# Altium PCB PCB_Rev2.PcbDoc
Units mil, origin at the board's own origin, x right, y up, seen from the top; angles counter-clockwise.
Board outline 1750.01 x 1055 mil, 4 copper layers (Top Layer, Layer 1 (GND), Layer 2 (PWR), Bottom Layer), stack 51.556 mil thick; 67 components, 50 nets, 281 pads, 118 vias.
Unrouted connection lines stored in the file: 3.
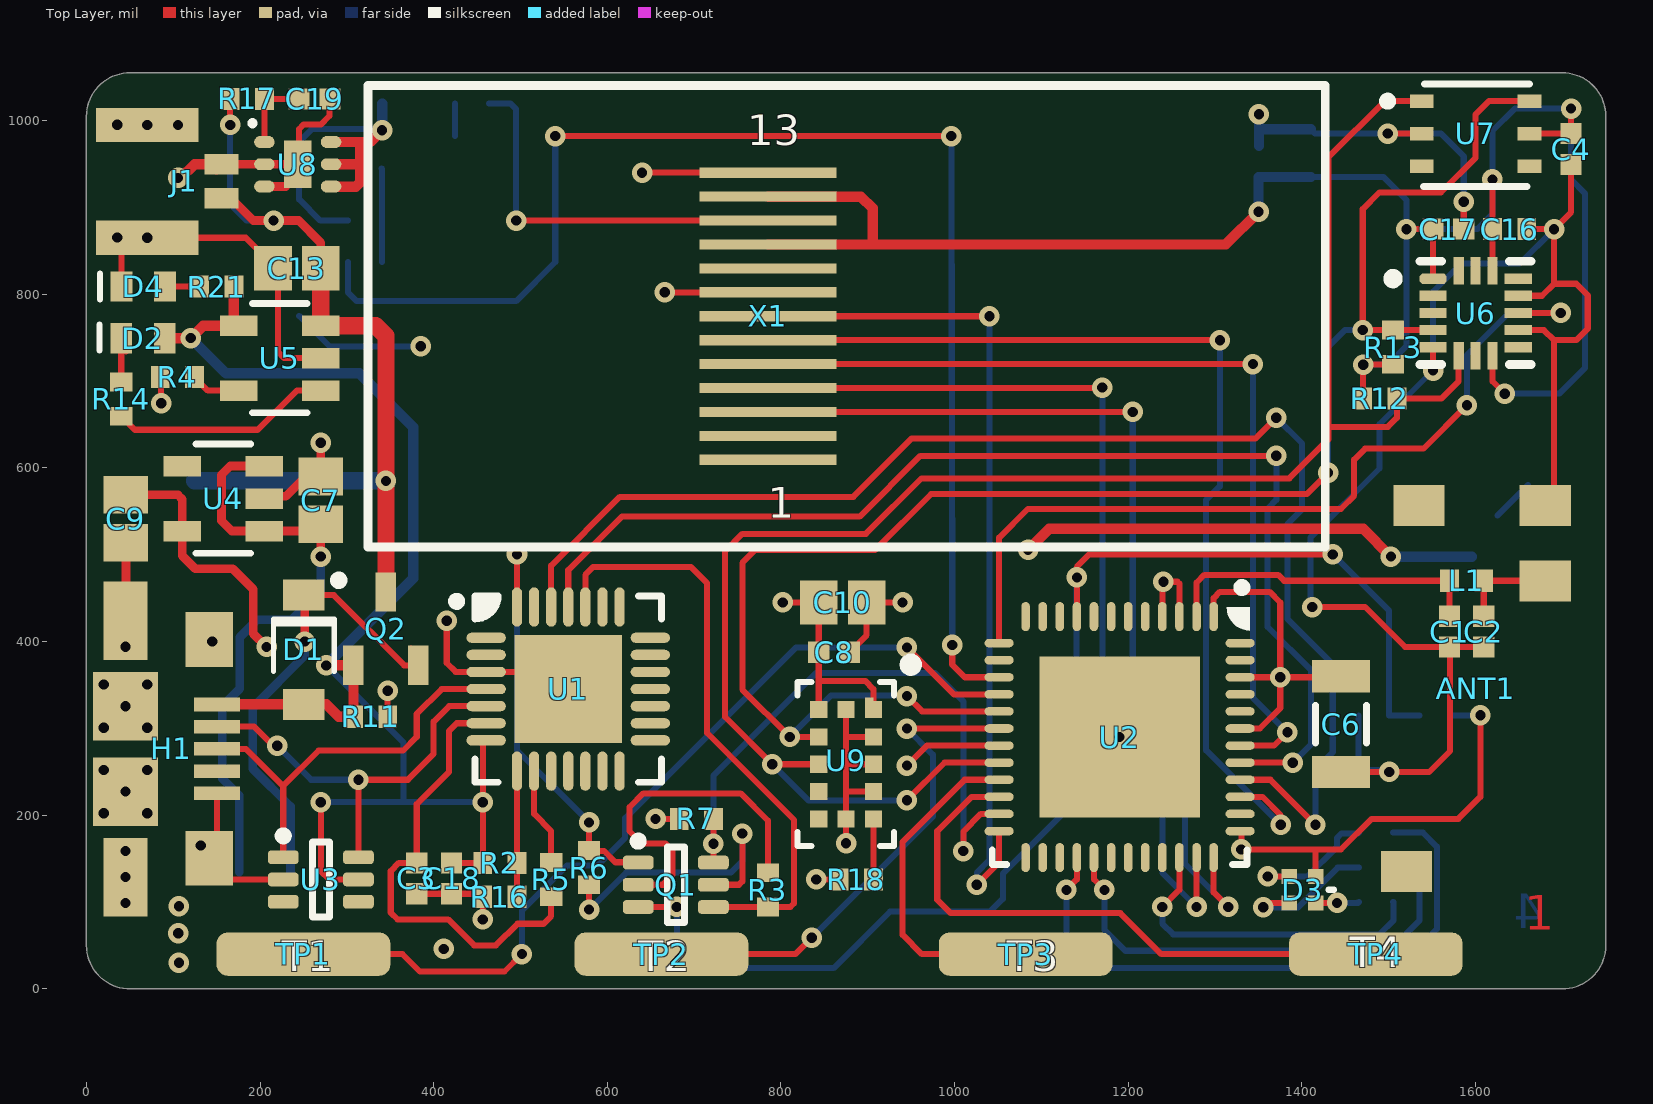
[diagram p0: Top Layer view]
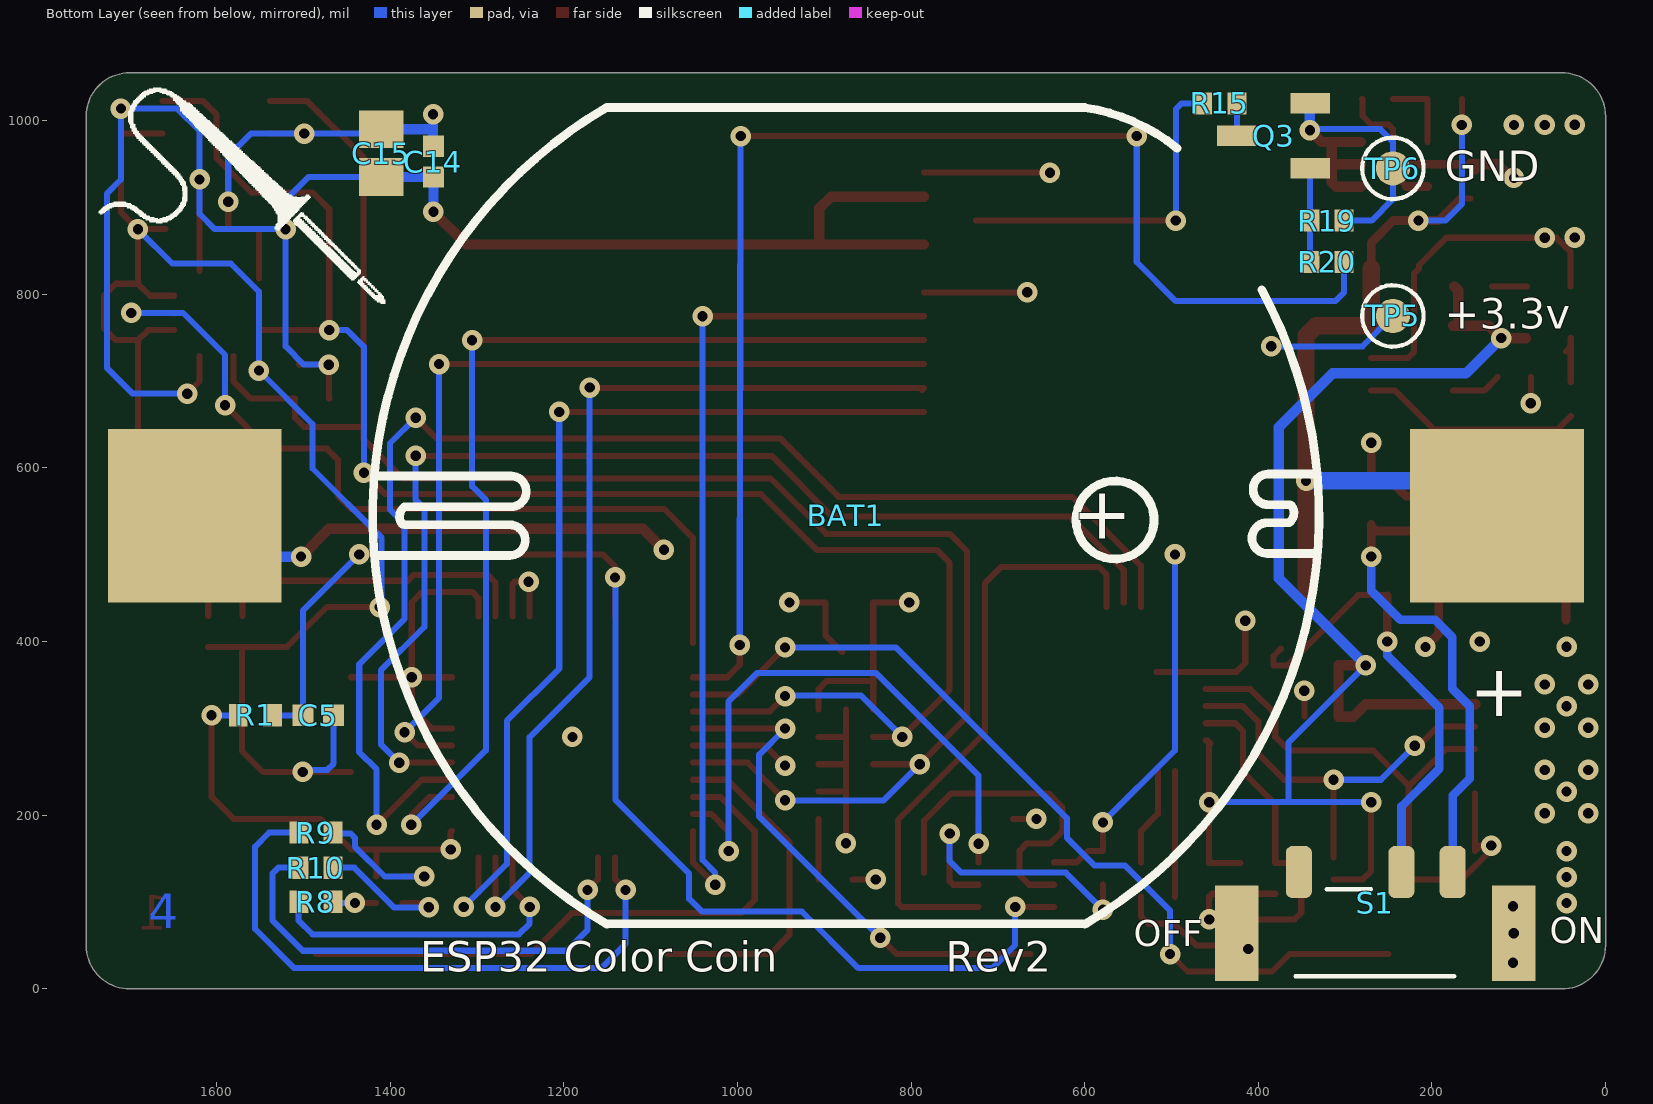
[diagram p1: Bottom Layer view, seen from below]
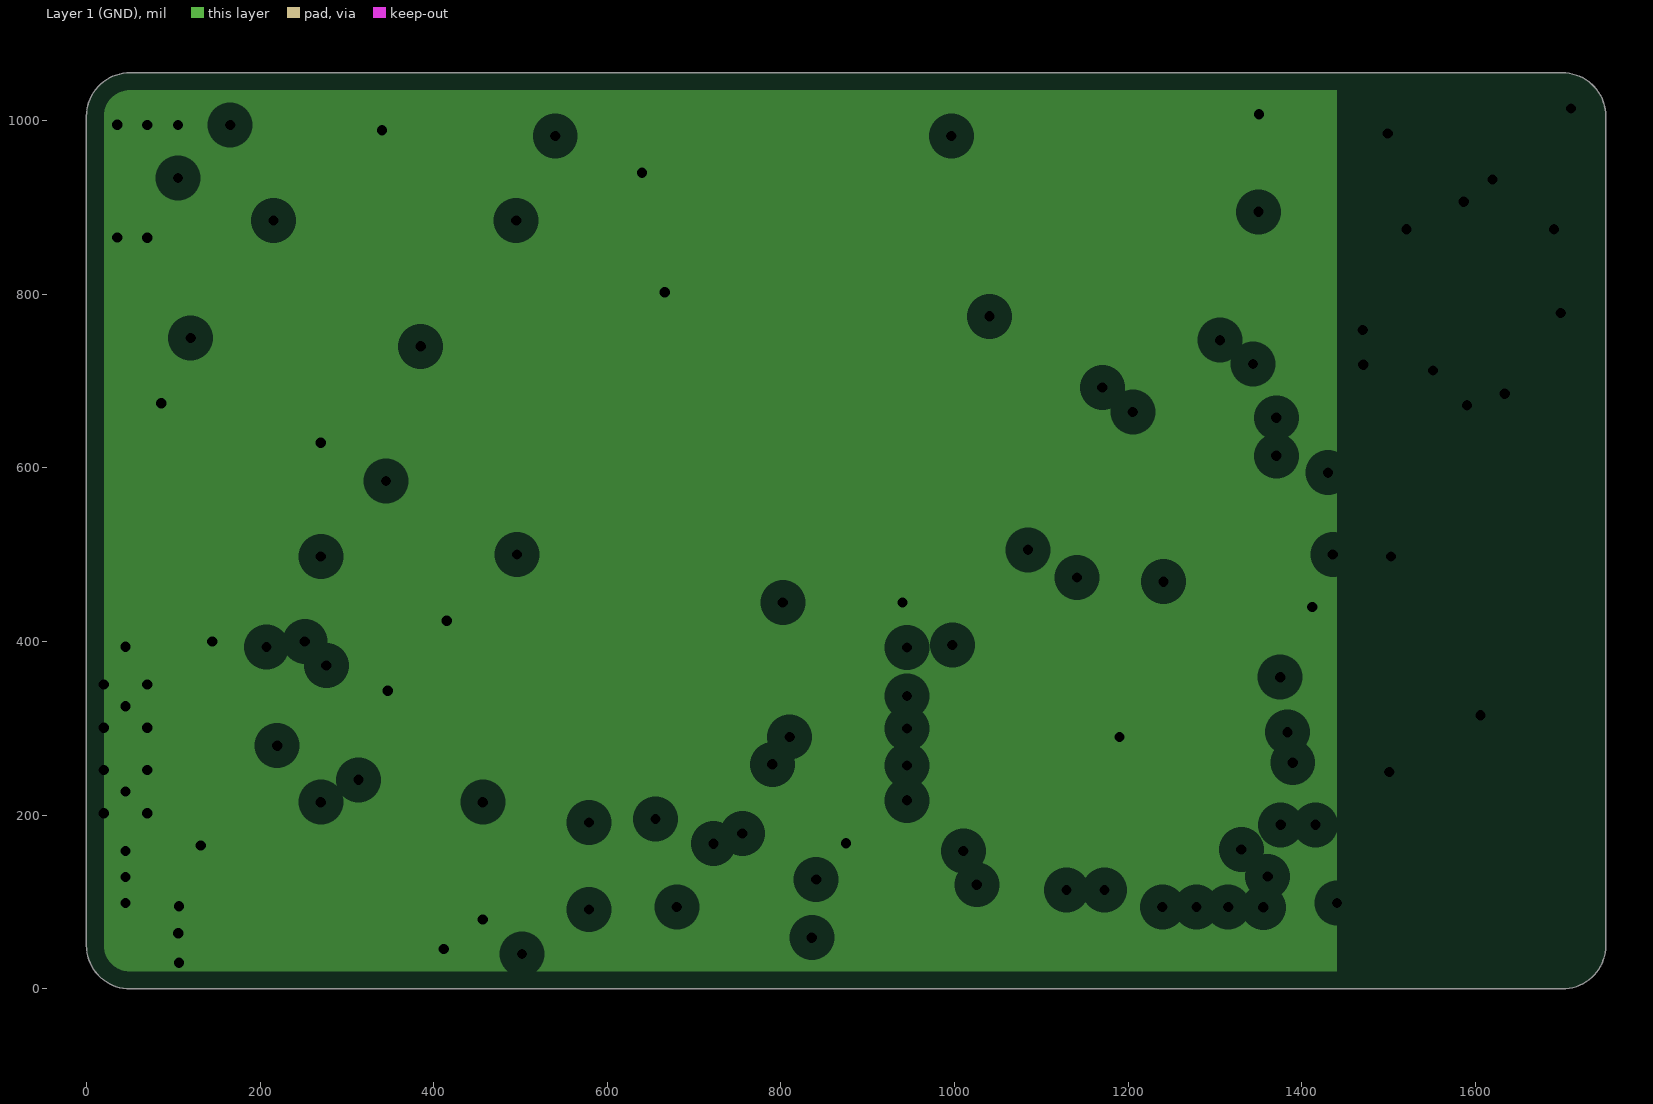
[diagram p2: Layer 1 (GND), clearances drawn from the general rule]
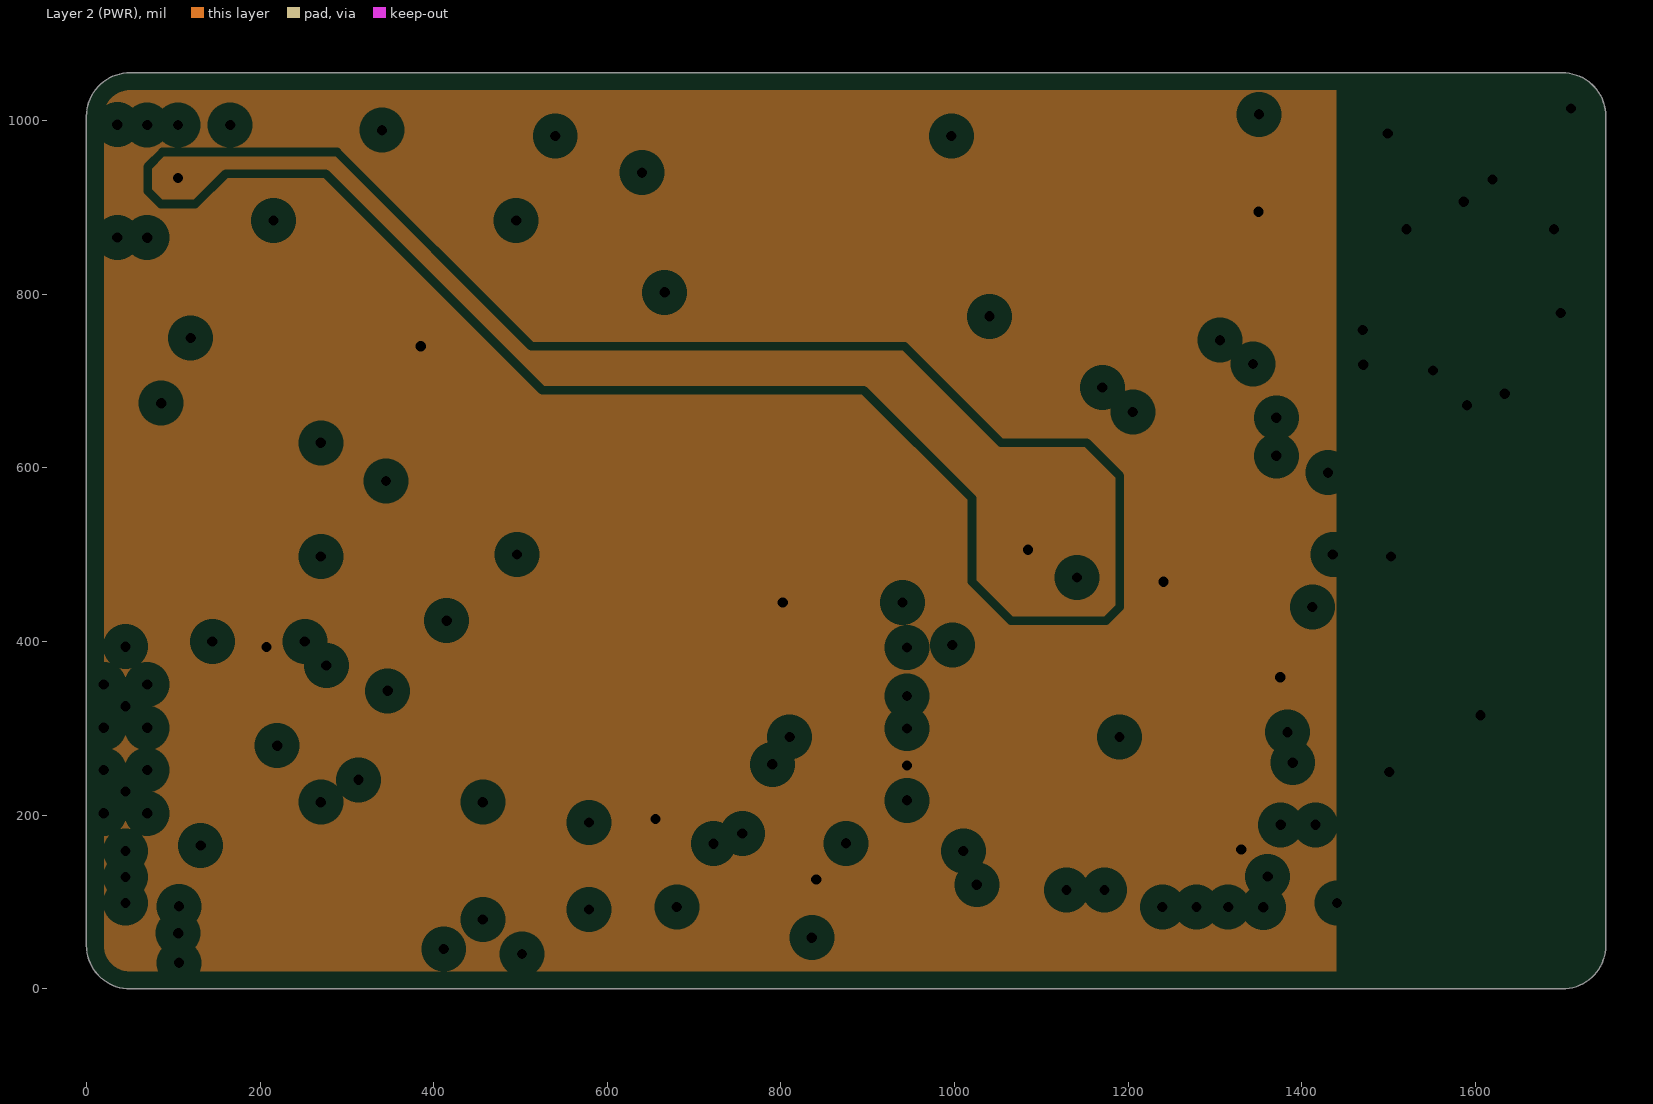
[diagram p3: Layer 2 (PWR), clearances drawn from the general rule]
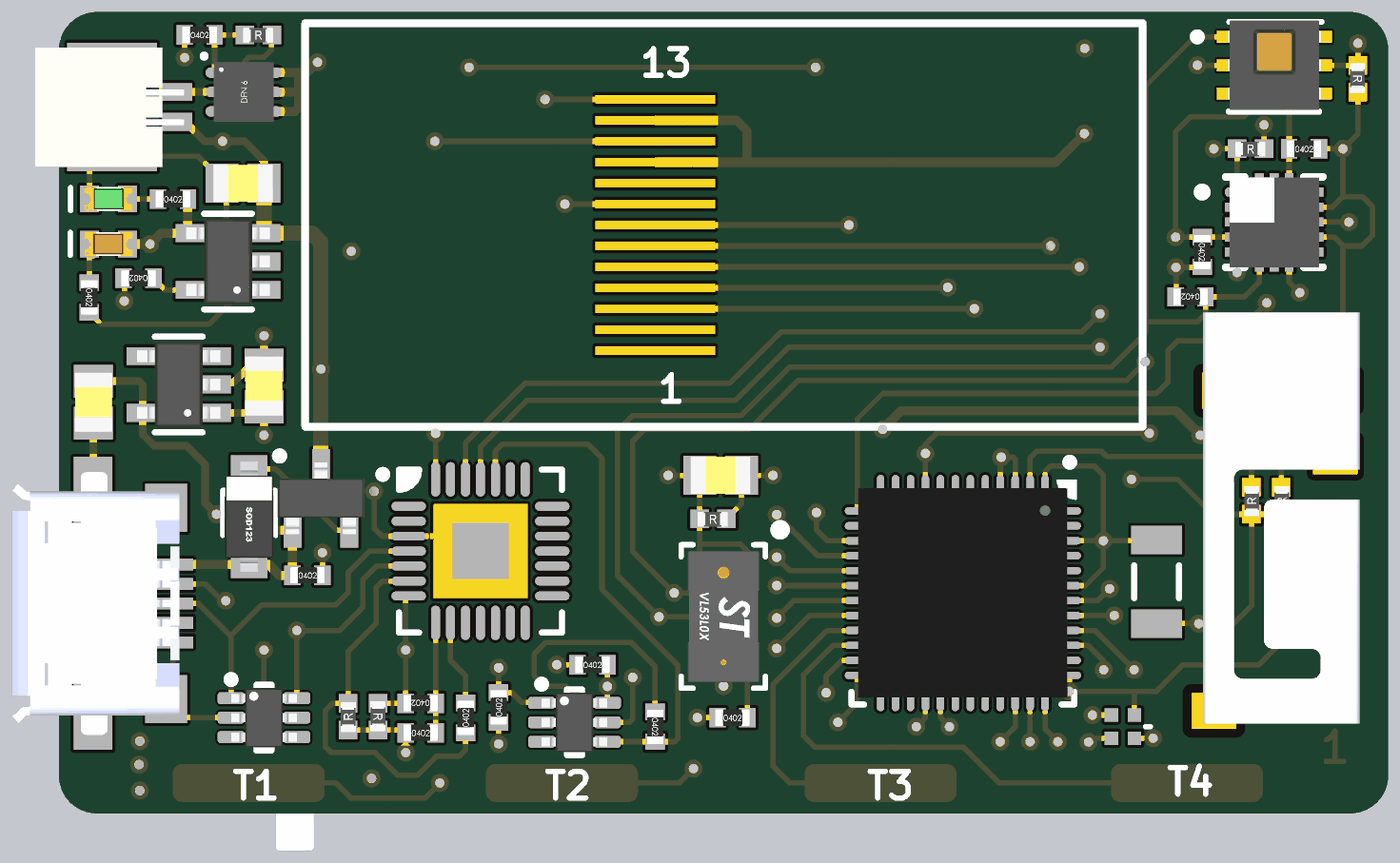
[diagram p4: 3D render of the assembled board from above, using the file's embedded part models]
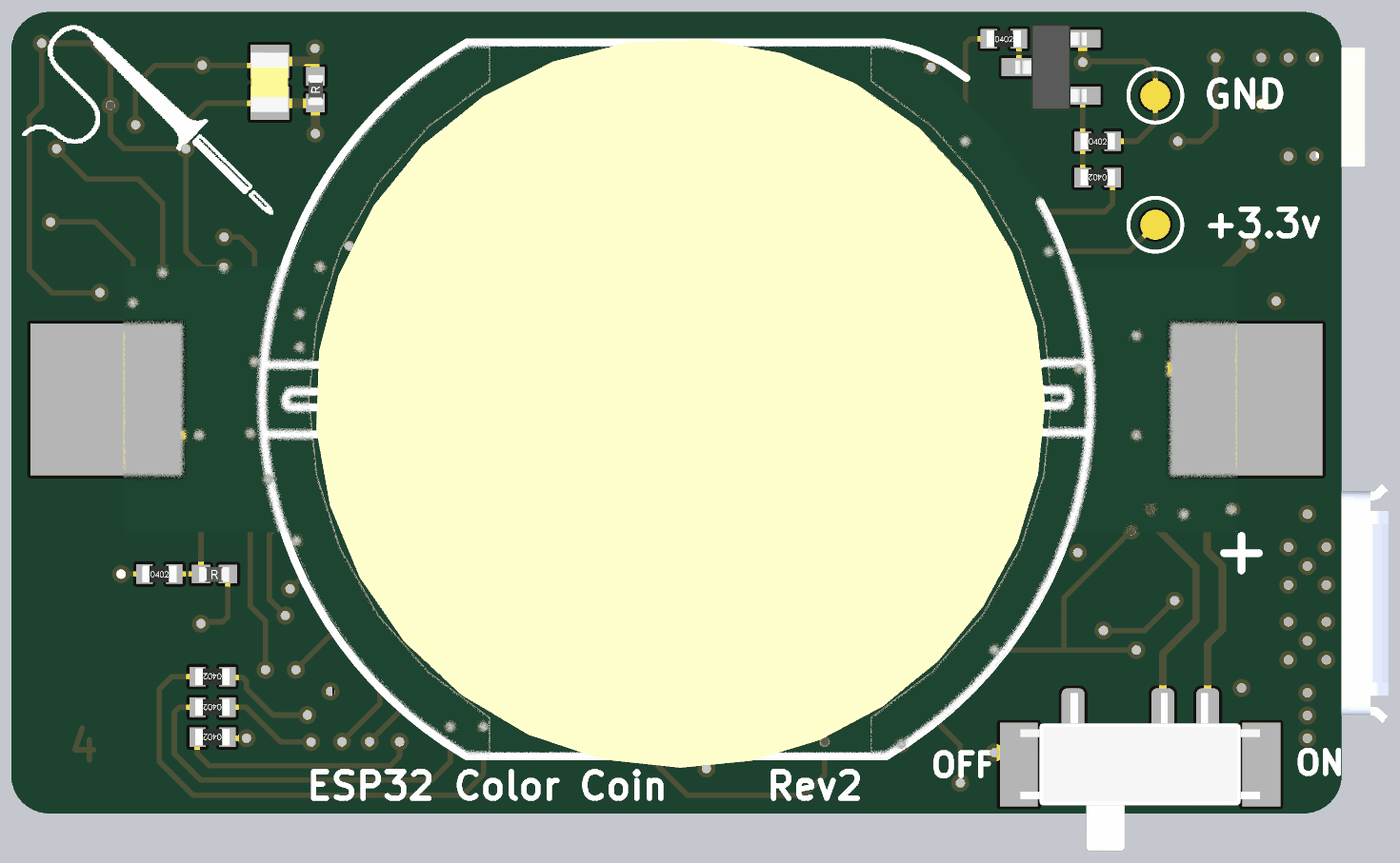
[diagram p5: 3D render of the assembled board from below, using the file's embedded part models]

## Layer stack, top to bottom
Top Solder: solder mask 0.4, Solder Resist, Dk 3.5
Top Layer: signal copper 1.4
Dielectric 2: prepreg 2.8, PP-006, Dk 4.1
Layer 1 (GND): plane copper 1.3778, net GND
Dielectric 1: dielectric 40.4, FR-4, Dk 4.8
Layer 2 (PWR): plane copper 1.3778, net (Multiple Nets)
Dielectric 3: prepreg 2.8, PP-006, Dk 4.1
Bottom Layer: signal copper 1.4
Bottom Solder: solder mask 0.4, Solder Resist, Dk 3.5

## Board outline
50.5,0 cw(c50,50) 0,50 0,1005 cw(c50,1005) 50.5,1055 1699.49,1055 cw(c1699.99,1005.01) 1749.99,1005.01 1750.01,50 cw(c1700.01,50) 1699.51,0

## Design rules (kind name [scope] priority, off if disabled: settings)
Clearance Clearance_U7 [All vs InComponent('U7')] p1: gap=7 ignorepadtopadclearanceinfootprint=FALSE
Clearance Clearance_H1 [All vs InComponent('H1')] p2: gap=9.5 ignorepadtopadclearanceinfootprint=FALSE
Clearance Clearance_U3 [All vs InComponent('U3')] p3: gap=9.5 ignorepadtopadclearanceinfootprint=FALSE
Clearance Clearance_Q1 [All vs InComponent('Q1')] p4: gap=9.5 ignorepadtopadclearanceinfootprint=FALSE
Clearance Clearance_X1 [All vs InComponent('X1')] p5: gap=8.5 ignorepadtopadclearanceinfootprint=FALSE
Clearance Clearance_U2 [All vs InComponent('U2')] p6: gap=9.5 ignorepadtopadclearanceinfootprint=FALSE
Clearance Clearance_U1 [All vs InComponent('U1')] p7: gap=7.8 ignorepadtopadclearanceinfootprint=FALSE
Clearance Clearance_U6 [All vs InComponent('U6')] p8: gap=7.5 ignorepadtopadclearanceinfootprint=FALSE
Clearance [All] p9: gap=10 ignorepadtopadclearanceinfootprint=FALSE except(0: Arc-Hole Track-Hole SMDPad-Hole THPad-Hole Via-Hole Fill-Hole Poly-Hole Region-Hole Text-Hole)
HoleSize [All] p1: absolutevalues=TRUE maxlimit=200 minlimit=1 maxpercent=80.000 minpercent=20.000
MinimumSolderMaskSliver MinimumSolderMaskSliver_X1 [All vs InComponent('X1')] p1: minsoldermaskwidth=0.6
MinimumSolderMaskSliver [All] p2: minsoldermaskwidth=1
PlaneClearance [All] p1: clearance=20
PlaneConnect [All] p1: planeconnectstyle=Direct reliefexpansion=20 reliefentries=4 reliefconductorwidth=10 reliefairgap=10
PolygonConnect [All] p1: connectstyle=Relief reliefconductorwidth=10 reliefentries=4 polygonreliefangle="90 Angle" airgapwidth=10
RoutingVias [All] p1: holewidth=11.81 width=23.62 viastyle="Through Hole" minholewidth=11.81 minwidth=23.62 maxholewidth=11.81 maxwidth=23.62
SilkToSilkClearance [All] p1: silktosilkclearance=5
SilkToSolderMaskClearance [IsPad] p1: minsilkscreentomaskgap=5 clearancetoexposedcopper=TRUE
SolderMaskExpansion [All] p1: expansion=4
Width [All] p1: maxlimit=40 minlimit=7 preferedwidth=7
24 further rules are at their usual default settings.

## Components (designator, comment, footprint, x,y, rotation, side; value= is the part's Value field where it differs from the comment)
ANT1 "RF ANT 2.4GHZ STAMPED MET SLD" PRO-OB-440 1680.37,556.61 r0 top locked
BAT1 "BATTERY-HOLDER (2450)" BU2450SM-JJ-GTR 875,545 r0 bottom locked value="Coin Cell Holder"
C1 "=Value" CAPC1005X56N#1 1570,411.5 r90 top
C2 "=Value" CAPC1005X56N#1 1609.37,411.5 r90 top
C3 "4.7uF" CAPC1005X56N#2 380.51,127.28 r90 top
C4 "0.1uF" CAPC1005X56N#1 1710,967.28 r270 top
C5 "0.1uF" CAPC1005X56N#2 1482.72,315 r180 bottom
C6 "100uF" CAPC3216X160L 1445,304.88 r270 top
C7 "10uF" CAPC2012X140N 270,562.56 r90 top
C8 "0.1uF" CAPC1005X56N#2 861.22,387.76 r0 top
C9 "10uF" CAPC2012X140N 45.51,541.34 r270 top
C10 "10uF" CAPC2012X140N 871.06,445 r0 top
C13 "10uF" CAPC2012X140N 242.44,829.76 r180 top
C14 "0.1uF" CAPC1005X56N#2 1350,952.72 r90 bottom
C15 "10uF" CAPC2012X140N 1410,962.56 r90 bottom
C16 "0.1uF" RESC1005X40L 1639.14,875 r0 top
C17 "0.1uF" CAPC1005X56N#2 1568.67,875 r0 top
C18 "1uF" CAPC1005X56N#2 420.51,127.28 r270 top
C19 "0.1uF" CAPC1005X56N#2 262.72,1025 r0 top
D1 "MBR0520" SOD123 250.51,390.56 r270 top
D2 "LED_0603" LED1608X55N-RED 65.14,749.53 r0 top value=Red
D3 "RGB" FC-B1010RGBT-HG 1400.77,114.15 r0 top value="RGB Led"
D4 "LED_0603" LED1608X55N-GREEN 65.51,808.9 r0 top locked value=Green
H1 "Micro USB" 1981584-1 97.66,276.38 r270 top
J1 "CON2" JST_Micro_2PIN 155.63,930.04 r270 top
L1 "Inductor" RESC1005X40L 1589.69,470 r180 top value=1.8nH
Q1 "BC847S" SOT65P210X110-6N 678.82,118.9 r0 top value=2NPN
Q2 "FDN340P" SOT95P240X110-3N 345,414.84 r90 top value="Mosfet P-H"
Q3 "MMBT3904" SOT95P240X110-3N 382.33,982.4 r0 bottom locked
R1 "10K" RESC1005X40L 1555.12,315 r180 bottom
R2 "22.1K" RESC1005X40L 476.26,145 r180 top
R3 "10K" RESC1005X40L 785,113.98 r270 top
R4 "43K" RESC1005X40L 104.83,704.53 r180 top
R5 "4.7K" RESC1005X40L 535.32,125.79 r90 top
R6 "10K" RESC1005X40L 578.94,139.57 r90 top
R7 "10K" RESC1005X40L 702.44,195.67 r0 top
R8 "1K" RESC1005X40L 1485.32,100.21 r0 bottom
R9 "1K" RESC1005X40L 1485.32,180 r0 bottom
R10 "1K" RESC1005X40L 1485.32,139.58 r0 bottom
R11 "100K" RESC1005X40L 327.28,313.5 r0 top
R12 "2K" RESC1005X40L 1489.69,680 r180 top
R13 "2K" RESC1005X40L 1505,739.06 r270 top
R14 "2K" RESC1005X40L 40.14,679.21 r270 top
R15 "22R" RESC1005X40L 444.33,1019.8 r180 bottom
R16 "47.5K" RESC1005X40L 476.26,106.1 r0 top
R17 "100R" RESC1005X40L 185.32,1025 r0 top
R18 "10K" RESC1005X40L 886.81,125.98 r0 top
R19 "10K" RESC1005X40L 320.83,884.88 r180 bottom
R20 "1K" RESC1005X40L 320.83,837.17 r0 bottom
R21 "2K" RESC1005X40L 150.32,808.9 r0 top
S1 "SWITCH SLIDE" K3-1296S-E1 265.14,99.53 r180 bottom
TP1 "Test Point, 1mm Top Layer" TP100TL#1 302.06,-135 r90 top
TP2 "Test Point, 1mm Top Layer" TP100TL#2 662.28,40 r90 top
TP3 "Test Point, 1mm Top Layer" TP100TL#3 580,-145 r90 top
TP4 "Test Point, 1mm Top Layer" TP100TL#4 945.51,-121.1 r90 top
TP5 "Test Point, 1mm Top Layer" TP100TL#5 245,775 r90 bottom
TP6 "Test Point, 1mm Top Layer" TP100TL#5 245,945 r90 bottom
U1 "CP2102N" 28-QFN 555,345.28 r0 top locked
U2 "ESP32-PICO-D4" QFN48 1190,290 r270 top locked
U3 "PESD5V0L5UY" SOT65P210X110-6N 270,125 r0 top value=ESD
U4 "HT7833" SOT95P280X144-5N 157.76,564.69 r180 top value="LDO 3.3V"
U5 "SL4054ST25P" SOT95P280X144-5N 222.76,726.5 r180 top
U6 "LIS3DHTR" QFN3X3_16_1.2 1599.96,777.99 r0 top
U7 "HDC1080DMBT" HDC1080 1600,985 r0 top value=Humidity/Temperature
U8 "XB6566H0" "DFN-6 2x2mm" 243.39,949.72 r0 top value="Battery Protection"
U9 "VL53L0CXV0DH" VL53L0CXV0DH 875,263.09 r0 top locked
X1 "TFT_0.96 inch" "TFT_GLASS 0.96 INCH" 966.1,774.65 r90 top locked

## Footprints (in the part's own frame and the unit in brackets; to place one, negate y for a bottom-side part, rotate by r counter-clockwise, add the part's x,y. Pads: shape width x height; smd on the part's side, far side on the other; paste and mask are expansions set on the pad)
28-QFN [mm] "QFN, 28-Leads, Body 5.00x5.00mm, Pitch 0.50mm, Thermal Pad 3.15x3.15mm, IPC Medium Density"
  oval 1.15x0.3 smd: 1(-2.4,1.5) 2(-2.4,1) 3(-2.4,0.5) 4(-2.4,0) 5(-2.4,-0.5) 6(-2.4,-1) 7(-2.4,-1.5) 15(2.4,-1.5) 16(2.4,-1) 17(2.4,-0.5) 18(2.4,0) 19(2.4,0.5) 20(2.4,1) 21(2.4,1.5)
  oval 0.3x1.15 smd: 8(-1.5,-2.4) 9(-1,-2.4) 10(-0.5,-2.4) 11(0,-2.4) 12(0.5,-2.4) 13(1,-2.4) 14(1.5,-2.4) 22(1.5,2.4) 23(1,2.4) 24(0.5,2.4) 25(0,2.4) 26(-0.5,2.4) 27(-1,2.4) 28(-1.5,2.4)
  rect 3.15x3.15 smd paste-0.635: 29(0,0)
  silkscreen extent -3.39,-2.73 2.73,2.73, body extent -2.58,-2.57 2.57,2.58, height 1
1981584-1 [mm] "CONN RCPT MICRO USB TYPE AB"
  rect 0.4x1.35 smd: 1(-1.3,1.338) 2(-0.65,1.338) 3(0,1.338) 4(0.65,1.338) 5(1.3,1.338)
  rect 2.3x1.3 smd: 6(-3.75,-1.337) 6(3.75,-1.337)
  rect 1.6x1.4 smd: 6(-3.2,1.113) 6(3.2,1.113)
  rect 2x1.9 smd: 6(-1.25,-1.337) 6(1.25,-1.337)
  body extent -4.4,-4.05 4.4,1.55, height 2.75
BU2450SM-JJ-GTR [mil] "HOLDER,BATT,COIN,24.5MM,SMT"
  rect 200x200 smd: 1(-750,0) 2(750,0)
  silkscreen extent -545,-470 545,470, body extent -842,-570 3485,485, height 291
CAPC1005X56N#1 [mm] "Chip Capacitor, 2-Leads, Body 1.0x0.5mm, IPC Medium Density (0402 ceramic)"
  rect 0.62x0.62 smd paste-0.305: 1(-0.45,0) 2(0.45,0)
  body extent -0.55,-0.3 0.55,0.3, height 0.6
CAPC1005X56N#2 [mm] "Chip Capacitor, 2-Leads, Body 1.0x0.5mm, IPC Medium Density (0402 ceramic)"
  rect 0.62x0.62 smd: 1(-0.45,0) 2(0.45,0)
  body extent -0.55,-0.3 0.55,0.3, height 0.6
CAPC2012X140N [mm] "Chip Capacitor, 2-Leads, Body 2.0x1.3mm, IPC Medium Density (0805 ceramic)"
  rect 1.1x1.3 smd: 1(-0.7,0) 2(0.7,0)
  body extent -1,-0.62 1,0.63, height 1.24
CAPC3216X160L [mm] "Chip Capacitor, 2-Leads, Body 3.2x1.6mm, IPC Least Density(C1206)"
  rect 0.95x1.7 smd: 1(-1.4,0) 2(1.4,0)
  silkscreen extent -0.55,-0.75 0.55,0.75, body extent -1.7,-0.9 1.7,0.9, height 1.9
"DFN-6 2x2mm" [mm] "DFN, 6-Leads, Body 2.00x2.00mm, Pitch 0.65mm, IPC High Density"
  oval 0.6x0.35 smd: 1(-0.975,0.65) 2(-0.975,0) 3(-0.975,-0.65) 4(0.975,-0.65) 5(0.975,0) 6(0.975,0.65)
  rect 0.8x1.4 smd paste-0.15: 7(0,0)
  silkscreen extent -1.37,1.15 -1.27,1.25, body extent -1,-1 2.65,1, height 4.99
FC-B1010RGBT-HG [mm] "LED,RGB,SMD,RoHS"
  rect 0.45x0.45 smd: 1(0.387,0.388) 2(0.387,-0.387) 3(-0.387,-0.387) 4(-0.387,0.388)
  silkscreen extent 0.76,0 0.91,0, body extent -0.53,-0.55 0.53,0.58, height 1.2
HDC1080 [mm] "Temp/Humidity Sensor"
  rect 0.7x0.4 smd paste-0.381 mask+0.076: 1(-1.575,0.95) 2(-1.575,0) 3(-1.575,-0.95) 4(1.575,-0.95) 5(1.575,0) 6(1.575,0.95)
  silkscreen extent -2.7,-1.55 1.57,1.45, body extent -1.55,-1.5 1.55,1.5, height 0.85
JST_Micro_2PIN [mm]
  rect 0.6x1 smd: 1(0.5,0) 2(-0.5,0)
  rect 1x3 smd: ""(-1.65,-2.175) ""(1.65,-2.175)
  body extent -1.99,-4.74 2,0.24, height 2.9
K3-1296S-E1 [mil] "Toggle Switches SMD RoHS"
  rrect50% 30x60 smd: 1(89.06,35) 2(30,35) 3(-88.11,35)
  rect 50x110 smd: 4(-159.45,-35.43) 4(159.45,-35.43)
  silkscreen extent -92,-85 91,15, body extent -157,-149 158,59, height 60
LED1608X55N-GREEN [mil] "Chip LED GREEN 2-Leads, Body 1.6x0.8mm, IPC Medium Density (0603 med)"
  rect 25x35 smd: 1(-25,0) 2(25,0)
  body extent -31,-16 32,16, height 24
LED1608X55N-RED [mil] "Chip LED RED, 2-Leads, Body 1.6x0.8mm, IPC Medium Density (0603 med)"
  rect 25x35 smd: 1(-25,0) 2(25,0)
  body extent -31,-16 31,16, height 24
PRO-OB-440 [mm] "RF ANT 2.4GHZ STAMPED MET SLD"
  rect 1.5x1.2 smd paste-0.762 mask+0.2: 1(0,0) 2(0,-2.2)
  rect 1.5x1.2 smd paste-0.762 mask+0.3: 3(-3.7,0) 4(-4.064,-10.709)
  body extent -4.42,-11.14 7.98,2.61, height 3.56
QFN3X3_16_1.2 [mm] "QFN3X3_16_1.2"
  oct 0.8x0.3 smd: 1(-1.245,1.016)
  rect 0.8x0.3 smd: 2(-1.245,0.514) 3(-1.245,0.013) 4(-1.245,-0.489) 5(-1.245,-0.991) 9(1.245,-0.991) 10(1.245,-0.489) 11(1.245,0.013) 12(1.245,0.514) 13(1.245,1.016)
  rect 0.3x0.8 smd: 6(-0.495,-1.245) 7(0,-1.245) 8(0.495,-1.245) 14(0.495,1.245) 15(0,1.245) 16(-0.495,1.245)
  silkscreen extent -2.54,-1.5 1.63,1.52, body extent -1.51,-1.5 1.51,1.5, height 0.81
QFN48 [mm] "QFN, 48-Leads, Body 7x7mm, Pitch 0.5mm, IPC Medium Density"
  oval 0.85x0.25 smd: 1(-3.525,2.75) 2(-3.525,2.25) 3(-3.525,1.75) 4(-3.525,1.25) 5(-3.525,0.75) 6(-3.525,0.25) 7(-3.525,-0.25) 8(-3.525,-0.75) 9(-3.525,-1.25) 10(-3.525,-1.75) 11(-3.525,-2.25) 12(-3.525,-2.75) 25(3.525,-2.75) 26(3.525,-2.25) 27(3.525,-1.75) 28(3.525,-1.25) 29(3.525,-0.75) 30(3.525,-0.25) 31(3.525,0.25) 32(3.525,0.75) 33(3.525,1.25) 34(3.525,1.75) 35(3.525,2.25) 36(3.525,2.75)
  oval 0.25x0.85 smd: 13(-2.75,-3.525) 14(-2.25,-3.525) 15(-1.75,-3.525) 16(-1.25,-3.525) 17(-0.75,-3.525) 18(-0.25,-3.525) 19(0.25,-3.525) 20(0.75,-3.525) 21(1.25,-3.525) 22(1.75,-3.525) 23(2.25,-3.525) 24(2.75,-3.525) 37(2.75,3.525) 38(2.25,3.525) 39(1.75,3.525) 40(1.25,3.525) 41(0.75,3.525) 42(0.25,3.525) 43(-0.25,3.525) 44(-0.75,3.525) 45(-1.25,3.525) 46(-1.75,3.525) 47(-2.25,3.525) 48(-2.75,3.525)
  rect 4.7x4.7 smd paste-0.5: 49(0,0)
  silkscreen extent -4.5,-3.72 3.72,3.81, body extent -3.52,-3.51 3.5,3.51, height 0.78
RESC1005X40L [mm] "Chip Resistor, 2-Leads, Body 1.0x0.5mm, IPC Medium Density (0402)"
  rect 0.55x0.65 smd: 1(-0.5,0) 2(0.5,0)
  body extent -0.57,-0.27 0.58,0.28, height 0.41
SOD123 [mil] "Molded Diode, 2-Leads, Body 2.85x1.8mm, IPC Medium Density (SOD123)"
  rect 36x48 smd: 1(-63,0) 2(63,0)
  silkscreen extent -85,-35 25,45, body extent -73,-31 73,31, height 50
SOT65P210X110-6N [mm] "SC70, 6-Leads, Body 2.4x2.2mm (max), Pitch 0.65mm, IPC Medium Density"
  rrect50% 0.9x0.4 smd mask+0.076: 1(-1.1,0.675) 2(-1.1,0.025) 3(-1.1,-0.625) 4(1.1,-0.625) 5(1.1,0.025) 6(1.1,0.675)
  silkscreen extent -1.22,-1.07 0.25,1.42, body extent -1.1,-0.97 1.1,1.01, height 0.99
SOT95P240X110-3N [mm] "SOT23, 3-Leads, Body 3.0x2.5mm (max), Pitch 0.95mm, IPC Medium Density"
  rect 1.15x0.6 smd: 1(-1.075,0.95) 2(-1.075,-0.95) 3(1.075,0)
  body extent -1.2,-1.45 1.2,1.45, height 0.99
SOT95P280X144-5N [mm] "SOT23, 5-Leads, Body 3.1x3.0mm (max), Pitch 0.95mm, IPC Medium Density (RFMD SOT23-5)"
  rect 1.1x0.6 smd: 1(-1.2,0.95) 2(-1.2,0) 3(-1.2,-0.95) 4(1.2,-0.95) 5(1.2,0.95)
  silkscreen extent -0.8,-1.6 0.8,1.6, body extent -1.4,-1.45 1.4,1.45, height 1.45
"TFT_GLASS 0.96 INCH" [mm] "TFT_GLASS 0.96 INCH"
  rect 0.3x4 smd paste-0.305: 1(-4.2,4.6) 2(-3.5,4.6) 3(-2.8,4.6) 4(-2.1,4.6) 5(-1.4,4.6) 6(-0.7,4.6) 7(0,4.6) 8(0.7,4.6) 9(1.4,4.6) 10(2.1,4.6) 11(2.8,4.6) 12(3.5,4.6) 13(4.2,4.6)
  silkscreen extent -6.75,-11.7 6.75,16.3, body extent -6.75,-11.7 6.75,16.2, height 2
TP100TL#1 [mil] "Test Point"
  rrect50% 50x200 smd paste-80 mask-50: 1(175,52.06)
TP100TL#2 [mil] "Test Point"
  rrect50% 50x200 smd paste-80 mask+3: 1(0,0)
TP100TL#3 [mil] "Test Point"
  rrect50% 50x200 smd paste-80 mask-50: 1(185,-501.73)
TP100TL#4 [mil] "Test Point"
  rrect50% 50x200 smd paste-80 mask+3: 1(161.1,-539.49)
TP100TL#5 [mil] "Test Point"
  round 39.37 smd paste-19.68 mask+3: 1(0,0)
  silkscreen extent -35,-35 35,35
VL53L0CXV0DH [mm] "IC,LASER SENSOR,12pin"
  rect 0.25x0.25 smd: 1(0.675,1.713)
  rect 0.5x0.5 smd: 1(0.8,1.488) 2(0.8,0.687) 3(0.8,-0.112) 4(0.8,-0.913) 5(0.8,-1.712) 6(0,-1.712) 7(-0.8,-1.712) 8(-0.8,-0.912) 9(-0.8,-0.112) 10(-0.8,0.688) 11(-0.8,1.488) 12(0,1.488)
  silkscreen extent 1.69,2.6 2.09,3, body extent -1.2,-2.3 8.9,4.1, height 13.75

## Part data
ANT1: library part PRO-OB-440, Manufacturer="Proant AB"
BAT1: library part BU2450SM-JJ-GTR, "HOLDER,BATT,COIN,24.5MM,SMT", Manufacturer=MPD
C1 C2: library part CAP_0402, "DNP"
C3: library part CAP_0603, "CAP CER 4.7uF 16V 0402"
C4 C5 C8 C17 C19: library part CAP_0402, "CAP CER 0.1uF 0402", Manufacturer=CCTC, PartNumber=TCC0402X5R104M160AT
C6: library part CAP_1206, "CAP CER 100uF 6.3V 1206", Manufacturer="Taiyo Yuden", PartNumber=JMK316BJ107ML-T
C7 C9 C10: library part CAP_0805, "CAP 10uF 0805", Manufacturer=Murata, PartNumber=GRM21BB31C106KE15L
C13: library part CAP_0805, "CAP CER 10uF 16V 0805", Manufacturer=Samsung, PartNumber=CL21A106KOQNNNG
C14 C16: library part CAP_0402, "CAP CER 0.1uF 0402"
C15: library part CAP_0805, "CAP 10uF 0805"
C18: library part CAP_0603, "CAP CER 1uF 16V 0402"
D1: library part MBR0520-TP, "DIODE SCHOTTKY 20V 500MA SOD123", Manufacturer=CJ
D2: "LED RED CLEAR 0603 SMD", Manufacturer=FNO, PartNumber=FC-DA1608HRK-620D
D3: library part FC-B1010RGBT-HG, "LED,RGB LED,SMD,RoHS", Manufacturer=Foshan
D4: "LED XXXX CLEAR 0603 SMD", Manufacturer=Lite-On
H1: library part 1981584-1, "CONN RCPT MICRO USB TYPE AB", Manufacturer="REG CON", PartNumber=C21377
J1: library part JST_Micro_CONN_2PIN, "JST MIcro CONN 2POS"
L1: "Inductor 1.8nH 0402", Manufacturer=GFBE, PartNumber=BKW0603UC1N8KGT
Q1: "TRANS 2NPN 44V 0.1A SC-70-6", Manufacturer=Changjiang
Q2: "MOSFET P-CH 20V 2A SOT-23", Manufacturer="On Semi"
Q3: library part MMBT3904-TP, "TRANSISTOR NPN GP 40V SOT23", Manufacturer="Micro Commercial"
R1 R3 R6 R7 R18 R19: library part RES_0402, "RES SMD 10K OHM 0402", Manufacturer=Guangdong, PartNumber=RC-02W1002FT
R2: library part RES_0603, "RES SMD 22.1K OHM 0402", Manufacturer=Yageo, PartNumber=RC0402FR-0722K1L
R4: library part RES_0603, "RES SMD 43K OHM 0402", Manufacturer=Uniroyal, PartNumber=0402WGF4302TCE
R5: library part RES_0603, "RES SMD 4.7K OHM 0402", Manufacturer=Yageo, PartNumber=RC0402FR-074K7L
R8 R9 R10 R20: library part RES_0402, "RES SMD 1K OHM 0402", Manufacturer=Yageo, PartNumber=RC0402FR-071KL
R11: library part RES_0603, "RES SMD 100K OHM 0402", Manufacturer="Uniroyal Elec", PartNumber=0402WGF1003TCE
R12 R13: library part RES_0402, "RES 2K 0402"
R14 R21: library part RES_0603, "RES SMD 2K OHM 1% 1/10W 0402", Manufacturer="LIZ Elec", PartNumber=CR0402FF2001G
R15: library part RES_0402, "RES 22R 0402"
R16: library part RES_0603, "RES SMD 47.5K OHM 0402", Manufacturer=Yageo, PartNumber=RC0402FR-0747K5L
R17: library part RES_0603, "RES SMD 100R OHM 1% 1/10W 0402", Manufacturer=Yageo, PartNumber=RC0402FR-07100RL
S1: library part K3-1296S-E1, "SWITCH SLIDE SMD", Manufacturer="Korean Hroparts Elec"
TP1 TP2 TP3 TP4 TP5 TP6: Manufacturer=N/A
U1: "IC BRIDGE USB TO UART 28QFN", Manufacturer="Silicon Labs", PartNumber=CP2102N-A01-GQFN28
U2: "RF Transceiver ICs QFN-48_7x7x05P RoHS", Manufacturer=Espressif
U3: "TVS SOT-363 RoHS", Manufacturer=Yenji
U4: "IC LDO 3.3V 0.5A SOT23-5", Manufacturer=Holtek
U5: "Charger IC Lithium-Ion/Polymer SOT23-5", Manufacturer=Techfuse
U6: library part E-05-177, "IC ACCEL 2-16G I2C/SPI 16LGA", Manufacturer=STMicro
U7: "Humidity/Temperature Sensor", Manufacturer="Texas Instruments"
U8: "IC Battery Protection", Manufacturer=XySemi
U9: "IC,LASER SENSOR,12pin", Manufacturer="ST MICRO", Part Number=VL53L0CXV0DH/1
X1: library part "TFT_GLASS 0.96 INCH COLOR", "0.96 INCH TFT GLASS COLOR", Manufacturer=BuyDisplay, PartNumber=ER-TFT0.96-1

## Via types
v1: diameter 23.62, hole 11.81, Top Layer to Bottom Layer, tented both sides, 118 vias

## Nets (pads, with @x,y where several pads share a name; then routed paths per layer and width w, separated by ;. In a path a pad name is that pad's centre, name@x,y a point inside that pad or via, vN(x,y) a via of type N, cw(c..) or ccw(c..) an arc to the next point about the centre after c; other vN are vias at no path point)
+3.3V: C4.1 C6.1 C8.1 C9.1 C10.1 C14.1 C15.1 C16.1 C17.1 D3.1 R1.1 R7.1 R12.2 R13.2 R18.1 TP5.1 U2.1 U2.3 U2.4 U2.19 U2.37 U2.43 U2.46 U4.5 U6.1 U6.8 U6.14 U7.5 U9.1 U9.11 X1.10 X1.12 | length 4161.8
  Top Layer w7: v1(655.51,195.67) R7.1 ; v1(802.13,445) C10.1 C8.1 843.5,354.71 ; v1(840.51,125.98) R18.1 ; U9.11 843.5,354.71 ; U9.1@906.5,321.65 906.5,345.28 897.07,354.71 843.5,354.71 ; v1(945,257.17) 967.99,280.16 U2.19 ; U2.4 1239.21,468.9 v1(1240.51,468.9) 1256.61,468.9 1258.9,466.61 U2.3 ; U2.1 1298.27,449.92 1305.51,457.17 1362.83,457.17 1375,445 v1(1375,358.9) ; U2.37 1329,181.73 1330.32,180.42 1330.14,180.25 v1(1330.14,160.53) 1415.51,160.53 ; U2.43 1351.46,299.84 1375,323.39 v1(1375,358.9) ; U2.46 v1(1375,358.9) ; D3.1 1415.51,129.92 1415.51,160.53 ; C6.1@1445,358.9 v1(1375,358.9) ; R12.2 1470.51,680.51 v1(1470.51,718.9) 1504.53,718.9 R13.2 ; v1(1520.37,875) C17.1 U6.1 ; v1(1605.51,315) 1605.51,221.1 1580.08,195.67 1480.14,195.67 1445,160.53 1415.51,160.53 ; U6.8 1619.46,699.55 v1(1633.48,685.53) ; U6.14 C16.1 v1(1619.46,932.17) ; U7.5 C4.1 v1(1710,1013.9)
  Top Layer w10: C9.1 105.51,568.9 110.51,563.9 U4.5 110.51,498.9 125.51,483.9 168.5,483.9 192.28,460.12 192.28,408.98 v1(207.48,393.78)
  Top Layer w12: X1.10 905.51,857.32 ; X1.12 891.97,912.44 905.51,898.9 905.51,857.32 ; v1(1350,895) 1312.33,857.32 905.51,857.32
  Bottom Layer w7: TP5.1 280,740 v1(385,740) ; C15.1 1494.01,935 1520.37,908.64 v1(1520.37,875) ; v1(1470.51,718.9) 1499.41,718.9 1520.37,739.86 v1(1520.37,875) ; R1.1 v1(1605.51,315) ; v1(1633.48,685.53) 1696.48,685.53 1726.2,715.25 1726.2,915.96 1710,932.17 v1(1710,1013.9) 1645.22,1013.9 1619.46,988.13 v1(1619.46,932.17) 1619.46,892.5 1601.96,875 v1(1520.37,875)
  Bottom Layer w12: v1(1350,895) C14.1 C15.1
BLUE: R9.2 U2.28 | length 713.5
  Top Layer w7: v1(1128.78,113.98) 1140.79,125.98 U2.28
  Bottom Layer w7: v1(1128.78,113.98) 1128.78,51.73 1156.61,23.9 1510.51,23.9 1555.51,68.9 1555.51,163.9 1539.41,180 R9.2
D+: H1.3 U1.4 U3.1 | length 471.1
  Top Layer w7: H1.3 183.5,276.38 226.02,233.86 ; U3.1 226.69,233.86 267.36,274.53 364.88,274.53 380.51,290.16 380.51,316.61 409.17,345.28 U1.4
D-: H1.2 U1.5 U3.6 | length 481.7
  Top Layer w7: H1.2 193.2,301.97 215.17,280 v1(219.67,280) ; U3.6 v1(313.31,240.79) 370.2,240.79 400,270.59 400,307.8 417.8,325.59 U1.5
  Bottom Layer w7: v1(219.67,280) 258.88,240.79 v1(313.31,240.79)
DC: U2.42 X1.5 | length 1059.7
  Top Layer w7: X1.5 v1(1343.51,719.53) ; U2.42 1367.8,280.16 v1(1383.23,295.59)
  Bottom Layer w7: v1(1343.51,719.53) 1343.51,335.31 v1(1383.23,295.59)
DTR: Q1.1 R6.2 U1.28 | length 498.4
  Top Layer w7: U1.28 v1(495.95,500.39) ; v1(578.94,191.69) R6.2 579.45,158.74 596.26,158.74 609.18,145.82 635.17,145.82 Q1.1
  Bottom Layer w7: v1(495.95,500.39) 495.95,274.69 v1(578.94,191.69)
EN: C5.1 Q1.3 R1.2 U2.9 | length 1518.5
  Top Layer w7: Q1.3 v1(680,94.29) ; U2.9 v1(1140.79,473.9) 1140.79,485.95 1155.24,500.39 v1(1435.51,500.39)
  Bottom Layer w7: v1(680,94.29) 680,50.51 706.61,23.9 860.51,23.9 925.51,88.9 1040.67,88.9 1055.51,103.74 1055.51,132.68 1140.51,217.68 1140.51,473.62 v1(1140.79,473.9) ; v1(1435.51,500.39) 1500.44,435.47 C5.1 R1.2
GND: ANT1.1 C1.1 C2.1 C3.1 C4.2 C5.2 C6.2 C7.2 C8.2 C9.2 C10.2 C13.2 C14.2 C15.2 C16.2 C17.2 C18.2 D4.1 H1.5 H1.6 J1. Q3.2 R4.2 R11.2 R16.1 R19.2 S1.4 TP6.1 U1.3 U1.29 U2.49 U3.2 U4.2 U5.2 U6.5 U6.10 U6.12 U7.2 U8.4 U8.5 U8.6 U9.2 U9.3 U9.4 U9.6 U9.12 X1.8 X1.13 | length 4373.6
  Top Layer w7: D4.1 40.51,848.89 56.7,865.08 v1(70,865.08) 183.5,865.08 214.88,833.7 C13.2 220.51,824.13 220.51,733.9 227.91,726.5 U5.2 ; H1.6@45,424.02 H1.6@45.51,424.53 ; v1(86.14,674.53) R4.2@86.14,704.53 ; H1.5 150.32,158.9 144.22,165 v1(131.58,165) 131.58,159.93 165.52,125.98 U3.2 ; U4.2 U4.2@207.48,567.17 ; C7.2@252.56,590.12 C7.2 ; U8.4 U8.4@282.01,923.9 ; 314.8,949.72 315.51,949.02 ; R11.2 v1(346.97,343.19) ; C3.1 C18.2 453.11,109.57 R16.1 455.51,105.04 456.58,103.98 v1(456.58,80) ; v1(415,424.02) 415,375.32 425.35,364.96 U1.3 U1.29@517.21,364.96 ; v1(640,940) X1.13 ; v1(666.1,802.2) X1.8 ; v1(875,167.68) U9.6 875,227.17 ; U9.12 875,260.47 ; 876.81,290.16 U9.2 ; C8.2 898.62,407.44 C10.2 v1(940,445) ; U9.4 875,227.17 ; U9.3 876.81,258.66 875,260.47 ; v1(1412.01,439.76) 1472.68,439.76 1518.66,393.78 C1.1 ; C6.2 v1(1500.51,249.76) 1546.38,249.76 1570.51,273.9 1570.51,393.27 C1.1 ; v1(1498.78,985) U7.2 ; v1(1550.96,712.17) U6.5 ; C17.2 v1(1586.39,906.51) ; C2.1 C1.1 ; U6.10 1678.68,758.74 1690.34,747.09 ; U6.12 1676.5,798.24 1690.34,812.07 ; C16.2 v1(1690.34,875) ; ANT1.1 1690.34,566.58 1690.34,747.09 ; C4.2 1710,894.66 v1(1690.34,875) ; 875,227.17 875,260.47 ; 1690.34,747.09 1715.92,747.09 1729.2,760.37 1729.2,798.79 1715.92,812.07 1690.34,812.07 ; 1690.34,812.07 v1(1690.34,875)
  Top Layer w10: H1.6@45.51,424.53 C9.2 ; U4.2@207.48,567.17 229.61,567.17 C7.2@252.56,590.12 ; C7.2 v1(270,628.9)
  Top Layer w12: U8.5 314.8,949.72 ; U8.6 315.51,975.32 ; U8.4@282.01,923.9 310.28,923.9 315.51,929.13 315.51,949.02 315.51,975.32 ; v1(340.51,988.9) 326.93,975.32 315.51,975.32
  Bottom Layer w7: TP6.1@250.51,939.49 TP6.1 ; R19.2 269.41,884.88 245,909.29 TP6.1 ; Q3.2 Q3.2@340.51,1019.29 ; v1(340.51,988.9) 339.29,990.12 259.29,990.12 245,975.83 TP6.1 ; C14.2 C14.2@1350.51,970.94 ; 1350.51,989.05 1351.58,990.12 ; C15.2 1415.12,985 v1(1498.78,985) 1560.24,985 1586.39,958.85 v1(1586.39,906.51) ; v1(1412.01,439.76) 1410.03,441.75 1410.03,520.07 1489.29,599.33 1489.29,650.5 v1(1550.96,712.17) 1550.96,803 1583.2,835.25 1650.58,835.25 v1(1690.34,875) ; C5.2 1465,259.41 1472.24,252.17 1498.11,252.17 v1(1500.51,249.76)
  Bottom Layer w12: v1(340.51,988.9) Q3.2@340.51,1019.29 ; C14.2@1350.51,970.94 1350.51,989.05 v1(1350.51,1007.17) ; 1351.58,990.12 C15.2
  other v1: 106.58,30 411.58,46 105.69,64.09 106.58,95 45,98.74 45,128.74 45,158.74 20,202.17 70,202.17 45,227.17 20,252.17 70,252.17 1190,290.16 20,300.59 70,300.59 45,325.59 20,350.59 70,350.59 45,394.02 145,400 35.63,865.35 35.63,995.35 70,995 105.63,995
GREEN: R10.2 U2.29 | length 562.8
  Top Layer w7: U2.29 1160.47,125.98 v1(1172.48,113.98)
  Bottom Layer w7: v1(1172.48,113.98) 1172.48,68.03 1196.61,43.9 1500.51,43.9 1535.51,78.9 1535.51,132.68 1528.61,139.58 R10.2
INT1: U2.13 U6.11 | length 983.4
  Top Layer w7: U2.13 1051.22,519.61 1084.51,552.9 1444.96,552.9 1460.14,568.08 1460.14,609.53 1472.78,622.17 1540,622.17 v1(1590,672.17) ; U6.11 1649.45,778 1649.94,778.49 v1(1698.2,778.49)
  Bottom Layer w7: v1(1590,672.17) 1590,730 1638.49,778.49 v1(1698.2,778.49)
IO0: Q1.6 R7.2 U2.23 | length 723.4
  Top Layer w7: Q1.6 v1(722.13,167.17) R7.2 ; v1(1010,158.74) 1010,181.18 1030.24,201.42 U2.23
  Bottom Layer w7: v1(722.13,167.17) 722.13,245.51 840.51,363.9 977.21,363.9 1010,331.1 v1(1010,158.74)
LCD_BL: R20.1 U2.15 | length 1566.6
  Top Layer w7: v1(540,982.17) v1(996.14,982.17) ; v1(997.28,396.02) 997.28,373.5 1011.89,358.9 U2.15
  Bottom Layer w7: R20.1 301.14,802.2 311.18,792.17 495,792.17 540,837.17 v1(540,982.17) v1@540,982.4 ; v1(996.14,982.17) v1(997.28,396.02)
NetANT1_2: ANT1.2 C2.2 L1.1 | length 111.8
  Top Layer w7: C2.2 L1.1 ANT1.2
NetBAT1_2: BAT1.2 C19.2 J1.2 U8.2 U8.3 U8.7 | length 895.8
  Top Layer w7: J1.2 J1.2@163.5,949.72 ; U8.7@229.61,924.13 243.39,937.91 243.39,943.82 245,945.43 245,990.35 250,995.35 270,995.35 280,1005.35 280,1024.57 C19.2
  Top Layer w10: J1.2@163.5,949.72 U8.2 U8.7 ; U8.3 U8.7@229.61,924.13
  Top Layer w12: v1(105.63,933.9) 108.78,933.9 124.6,949.72 J1.2 J1.2@149.82,943.91 ; v1(1084.51,505.63) 1108.88,530 1470.41,530 v1(1502.51,497.9)
  Bottom Layer w7: BAT1.2 BAT1.2@1660.51,580.51
  Bottom Layer w12: v1(1502.51,497.9) BAT1.2@1595.9,497.9
NetC1_2: C1.2 L1.2 U2.2 | length 377.8
  Top Layer w7: U2.2 1278.58,467.8 1287.64,476.85 1372.56,476.85 1379.41,470 L1.2 C1.2
NetC3_2: C3.2 R5.1 U1.6 | length 532.5
  Top Layer w7: U1.6 426.58,305.91 417.8,297.13 417.8,249.96 380.51,212.68 C3.2 359.88,145 350.51,135.63 350.51,87.8 358.31,80 416.58,80 446.58,50 471.58,50 496.58,75 526.61,75 535.32,83.7 R5.1
NetC7_1: C7.1 S1.1 U4.1 U4.3 | length 708
  Top Layer w7: C7.1@262.28,527.28 C7.1
  Top Layer w10: U4.3 165.63,602.09 155.63,592.09 155.63,538.98 167.32,527.28 U4.1 C7.1@262.28,527.28 ; v1(270,497.9) C7.1
  Bottom Layer w10: S1.1 176.09,222.65 156.58,242.17 156.58,325.59 176.58,345.59 176.58,405 196.58,425 236.58,425 270,458.43 v1(270,497.9)
NetC19_1: C19.1 R17.2 U8.1 | length 89.7
  Top Layer w7: U8.1 R17.2 C19.1
NetD1_1: D1.1 Q2.2 S1.2 | length 550.4
  Top Layer w7: D1.1@251.58,452.5 D1.1 285.07,453.56 366.11,372.52 Q2.2 382.4,383.35 Q2.2@374.09,391.66
  Top Layer w10: v1(251.58,400) D1.1@251.58,452.5
  Bottom Layer w10: S1.2 235.14,210 191.58,253.57 191.58,323.9 251.58,383.9 v1(251.58,400)
NetD2_1: D2.1 R14.1 | length 57.7
  Top Layer w7: R14.1 D2.1 ; D2.1@40.51,738.9 D2.1@45.51,733.9
NetD3_2: D3.2 R8.1 | length 50.2
  Top Layer w7: D3.2 v1(1440.51,98.9)
  Bottom Layer w7: v1(1440.51,98.9) 1464.32,98.9 R8.1
NetD3_3: D3.3 R10.1 | length 161.1
  Top Layer w7: v1(1355.51,93.9) 1360.51,98.9 D3.3
  Bottom Layer w7: v1(1355.51,93.9) 1395.51,93.9 1441.2,139.58 R10.1
NetD3_4: D3.4 R9.1 | length 156.9
  Top Layer w7: v1(1360.51,129.41) D3.4
  Bottom Layer w7: v1(1360.51,129.41) 1406.02,129.41 1440.51,163.9 1440.51,173.9 1445.51,178.9 1464.53,178.9 R9.1
NetD4_2: D4.2 R21.1 | length 40.1
  Top Layer w7: D4.2 R21.1
NetQ1_2: Q1.2 R3.1 | length 397.8
  Top Layer w7: Q1.2 663.9,119.88 675,130.98 675,159.25 667.09,167.17 640.08,167.17 625.51,181.73 625.51,209.24 641.47,225.2 753.47,225.2 785,193.67 R3.1
NetQ1_5: Q1.5 R6.1 | length 355.1
  Top Layer w7: v1(578.94,91.26) R6.1 ; Q1.5 751.5,119.88 755.51,123.9 v1(755.51,178.9) 758.78,178.9 v1@760,177.68
  Bottom Layer w7: v1(578.94,91.26) 621.58,133.9 742.24,133.9 755.51,147.17 v1(755.51,178.9)
NetQ3_1: Q3.1 R19.1 R20.2 | length 108
  Bottom Layer w7: Q3.1 340.51,944.49 R19.1 R20.2
NetQ3_3: Q3.3 R15.2 | length 37.4
  Bottom Layer w7: Q3.3 R15.2
NetR2_1: R2.1 R16.2 U1.8 | length 144.7
  Top Layer w7: R16.2 R2.1 U1.8
NetR4_1: R4.1 U5.5 | length 57.4
  Top Layer w7: R4.1 139.94,689.09 U5.5
NetR5_2: R5.2 U1.9 | length 113.5
  Top Layer w7: U1.9 515.63,201.42 535.32,181.73 R5.2
NetR14_2: R14.2 U5.1 | length 255.1
  Top Layer w7: R14.2 55.77,643.9 197.28,643.9 242.48,689.09 U5.1
NetR15_1: R15.1 X1.11 | length 392
  Top Layer w7: v1(495,884.88) X1.11@725,884.88
  Bottom Layer w7: R15.1 488.31,1019.8 495,1013.11 v1(495,884.88)
RED: R8.2 U2.34 | length 385.7
  Top Layer w7: v1(1239.21,94.29) 1258.9,113.98 U2.34
  Bottom Layer w7: v1@1240.51,92.99 v1(1239.21,94.29) 1239.21,75.2 1251.73,62.68 1489.29,62.68 1505.51,78.9 1505.51,99.7 R8.2
RST: U2.39 X1.6 | length 1187.5
  Top Layer w7: X1.6 v1(1305.51,747.09) ; U2.39 1354.57,221.1 1375.51,200.16 v1(1375.51,188.9)
  Bottom Layer w7: v1(1305.51,747.09) 1305.51,578.9 1289.69,563.08 1289.69,274.72 v1(1375.51,188.9)
RTS: Q1.4 R3.2 U1.24 | length 693.7
  Top Layer w7: U1.24 574.69,476.85 583.78,485.95 696.22,485.95 715,467.17 715,294.67 815,194.67 815,98.39 810.9,94.29 R3.2 Q1.4
RXD: U1.26 U2.40 | length 1579.8
  Top Layer w7: U1.26 535.32,487.48 614.41,566.58 883.19,566.58 950.51,633.9 1346.65,633.9 v1(1370.51,657.76) ; U2.40 1363.62,240.79 v1(1415.51,188.9)
  Bottom Layer w7: v1(1370.51,657.76) 1400.14,628.13 1400.14,552.18 1383.2,535.25 1383.2,426.19 1435.51,373.88 1435.51,272.68 1415.51,252.68 v1(1415.51,188.9)
SCL: R13.1 U2.17 U6.4 U7.6 U9.10 | length 1928.8
  Top Layer w7: U9.10 v1(810,290.16) 755.51,344.65 755.51,490.63 770.51,505.63 908.46,505.63 972.73,569.9 1405.51,569.9 v1(1430.14,594.53) ; v1(945,337.17) 962.64,319.53 U2.17 ; U6.4 R13.1 v1(1470,758.74) 1470,898.08 1489.08,917.17 1560,917.17 1600,957.17 1600,1007.17 1615.24,1022.4 U7.6
  Bottom Layer w7: v1(810,290.16) 857.83,337.99 944.17,337.99 v1(945,337.17) ; v1(1430.14,594.53) 1430.14,739.53 1449.36,758.74 v1(1470,758.74)
SDA: R12.1 U2.20 U6.6 U7.1 U9.9 | length 2039.3
  Top Layer w7: U9.9 v1(790,258.66) 735.51,313.15 735.51,503.9 755.51,523.9 897.8,523.9 961.8,587.9 1385.51,587.9 1430.51,632.9 1430.51,647.17 ; v1(945,217.17) 988.31,260.47 U2.20 ; U7.1 1495.24,1022.4 1430.51,957.68 1430.51,647.17 ; U6.6 1580.46,699.55 1560.91,680 R12.1 1509.37,657.76 1498.78,647.17 1430.51,647.17
  Bottom Layer w7: v1(790,258.66) 831.5,217.17 v1(945,217.17)
SPI_CLK: U2.35 X1.4 | length 1088.7
  Top Layer w7: X1.4@787.44,689.53 X1.4 v1@1170.14,691.97 ; v1(1278.58,94.29) U2.35
  Bottom Layer w7: v1(1170.14,692.53) 1170.14,358.9 1239.21,289.83 1239.21,133.66 v1(1278.58,94.29)
SPI_MOSI: U2.36 X1.3 | length 1099.6
  Top Layer w7: X1.3 v1(1205.14,664.41) ; U2.36 1298.27,111.02 v1(1315,94.29)
  Bottom Layer w7: v1(1205.14,664.41) 1205.14,368.9 1265.51,308.53 1265.51,143.78 v1(1315,94.29)
TFT_CS: U2.24 X1.7 | length 988.6
  Top Layer w7: X1.7 v1(1040,774.65) ; v1(1025.51,119.88) 1051.22,145.59 U2.24
  Bottom Layer w7: v1(1025.51,119.88) 1025.51,133.9 1040,148.39 v1(1040,774.65) v1@1040,775
TOUCH_1: TP1.1 U2.16 | length 1029
  Top Layer w7: TP1.1 364.09,40 384.09,20 481.58,20 v1(501.58,40) ; v1(945,393.27) 999.06,339.21 U2.16
  Bottom Layer w7: v1(501.58,40) 501.58,90 553.74,142.17 588.78,142.17 620.51,173.9 620.51,196.46 817.32,393.27 v1(945,393.27)
TOUCH_2: TP2.1 U2.18 | length 601.7
  Top Layer w7: TP2.1 816.61,40 v1(835.51,58.9) ; v1(945,299.84) U2.18
  Bottom Layer w7: v1(835.51,58.9) 975,198.39 975,269.84 v1(945,299.84) v1@942.68,302.17
TOUCH_3: TP3.1 U2.21 | length 398.8
  Top Layer w7: U2.21 1011.58,240.79 940,169.21 940,62.17 962.17,40 TP3.1
TOUCH_4: TP4.1 U2.22 | length 697.5
  Top Layer w7: U2.22 1019.45,221.1 980,181.65 980,102.6 995.43,87.17 1190.89,87.17 1238.06,40 TP4.1
TXD: U1.25 U2.41 | length 1354.9
  Top Layer w7: U1.25@555,445 555,482.17 616.73,543.9 890.51,543.9 960.51,613.9 v1(1370.51,613.9) ; U2.41 v1(1389.41,260.47)
  Bottom Layer w7: v1(1370.51,613.9) 1370.51,563.08 1360.51,553.08 1360.51,416.73 1410.51,366.73 1410.51,281.57 v1(1389.41,260.47)
VBAT: BAT1.1 C13.1 J1.1 Q2.3 R17.1 U5.3 | length 1005.3
  Top Layer w7: J1.1 J1.1@166.81,910.35 ; v1(165.63,995) R17.1
  Top Layer w10: J1.1@166.81,910.35 192.28,884.88 v1(215.51,884.88) 244.53,884.88 270,859.41 C13.1
  Top Layer w20: C13.1 U5.3 333.27,763.9 345,752.17 Q2.3
  Bottom Layer w7: v1(165.63,995) 165.63,903.78 184.53,884.88 v1(215.51,884.88)
  Bottom Layer w20: BAT1.1@124.49,585 v1(345,585)
VUSB: C18.1 D1.2 D2.2 H1.1 Q2.1 R2.2 R11.1 R21.2 U1.7 U3.5 U5.4 | length 1702.1
  Top Layer w7: U5.4@169.82,772.21 168.51,770.9 U5.4 ; R21.2@169.82,804.35 169.82,808.72 R21.2 ; v1(270,215) 270,135.63 279.65,125.98 U3.5 ; C18.1 R2.2 455.14,146.43 456.58,147.87 v1(456.58,215) 456.58,281.13 455.14,282.57 458.8,286.22 U1.7
  Top Layer w12: D2.2@92.14,749.53 v1(120.14,749.53) 134.51,763.9 U5.4 ; H1.1 D1.2 276.38,327.56 290.43,313.5 R11.1 Q2.1 v1(276.38,372.52) ; U5.4@169.82,772.21 169.82,804.35 R21.2@174.37,808.9
  Bottom Layer w7: v1(270,215) 365,215 ; v1(276.38,372.52) 365,283.9 365,215 ; v1(456.58,215) 365,215
  Bottom Layer w12: v1(120.14,749.53) 160.77,708.9 314.51,708.9 376.51,646.9 376.51,472.65 v1(276.38,372.52)
XSHUT: R18.2 U9.5 | length 69.7
  Top Layer w7: R18.2 U9.5
pads on no net: ANT1.3 ANT1.4 H1.4 S1.3 U1.1 U1.2 U1.10 U1.11 U1.12 U1.13 U1.14 U1.15 U1.16 U1.17 U1.18 U1.19 U1.20 U1.21 U1.22 U1.23 U1.27 U2.5 U2.6 U2.7 U2.8 U2.10 U2.11 U2.12 U2.14 U2.25 U2.26 U2.27 U2.30 U2.31 U2.32 U2.33 U2.38 U2.44 U2.45 U2.47 U2.48 U3.3 U3.4 U4.4 U6.2 U6.3 U6.7 U6.9 U6.13 U6.15 U6.16 U7.3 U7.4 U9.7 U9.8 X1.1 X1.2 X1.9

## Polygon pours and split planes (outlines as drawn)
GND on Layer 1 (GND) (split plane): 50.5,1034.9 50.55,1034.9 1440.51,1034.9 1440.51,20.1 50.5,20.1 49.76,20.02 45.31,20.37 40.73,21.47 36.38,23.27 32.37,25.73 28.79,28.79 25.74,32.37 23.28,36.38 21.48,40.73 20.38,45.31 20.05,49.49 20.1,50 20.1,1005 20.05,1005.5 20.38,1009.69 21.48,1014.27 23.28,1018.61 25.74,1022.63 28.79,1026.21 32.37,1029.26 36.38,1031.72 40.73,1033.52 45.31,1034.62 49.76,1034.97
+3.3V on Layer 2 (PWR) (split plane): 50.5,1034.9 50.55,1034.9 1440.01,1034.9 1440.01,20.1 50.5,20.1 49.76,20.02 45.31,20.37 40.73,21.47 36.38,23.27 32.37,25.73 28.79,28.79 25.74,32.37 23.28,36.38 21.48,40.73 20.38,45.31 20.05,49.49 20.1,50 20.1,1005 20.05,1005.5 20.38,1009.69 21.48,1014.27 23.28,1018.61 25.74,1022.63 28.79,1026.21 32.37,1029.26 36.38,1031.72 40.73,1033.52 45.31,1034.62 49.76,1034.97
NetBAT1_2 on Layer 2 (PWR) (split plane): 508.85,736.4 510.51,735.29 512.46,734.9 940.05,734.9 1049.66,625.29 1051.32,624.19 1053.27,623.8 1149.91,623.8 1184.9,588.81 1184.9,441.88 1172.14,429.11 1066.99,429.11 1025.1,471.01 1025.1,565 1024.71,566.95 1023.6,568.6 899.08,693.13 897.42,694.24 895.47,694.63 526.99,694.63 279.12,942.5 277.46,943.61 275.51,944 160.51,944 158.56,943.61 156.91,942.5 123.4,909 87.62,909 75.61,921.01 75.61,944.58 89.83,958.8 286.45,958.8

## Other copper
Top Layer:
  text "1" at 1656.21,68.06 h40
Bottom Layer:
  text "4" at 1678.5,70 h40
Layer 1 (GND) (plane layer: these items are gaps in the copper):
  pour cut-out: 1441.01,1055 1440.51,1054.5 1440.51,0 1750.01,0 1749.99,0.02 1749.99,1055 1440.51,1055
  text "2" at 1650.88,68.06 h40
Layer 2 (PWR) (plane layer: these items are gaps in the copper):
  pour cut-out: 1440.51,1065 1440.01,1064.5 1440.01,10 1749.5,10 1749.49,10.01 1749.49,1065 1440.01,1065
  lines w10: 1538.51,448.9 1547.51,457.9 ; 70.51,918.9 70.51,946.69 87.72,963.9 288.56,963.9 512.46,740 942.17,740 1053.27,628.9 1152.03,628.9 1190,590.92 1190,439.76 1174.25,424.02 1064.88,424.02 1020,468.9 1020,565 895.47,689.53 524.88,689.53 275.51,938.9 160.51,938.9 125.51,903.9 85.51,903.9 70.51,918.9
  text "3" at 1650.56,66.22 h40

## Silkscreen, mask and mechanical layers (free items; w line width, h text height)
Top Overlay:
  lines w7: 15,735 15,765 ; 15.51,793.9 15.51,823.9 ; 819.19,180.48 819.19,164.67 835,164.67 ; 819.19,337.83 819.19,353.64 835,353.64 ; 914.3,164.67 930.12,164.67 930.12,180.48 ; 914.3,353.64 930.12,353.64 930.12,337.83
  text "T4" at 1455,25 h35
  text "T1" at 225,20 h35
  text "T2" at 635.71,20 h35
  text "T3" at 1060.08,20 h35
Bottom Overlay:
  drawing of 541 lines, arcs and shapes, not listed
  text "GND" at 185,930 h35
  text "+3.3v" at 185,760 h35
  text "Rev2" at 760.14,19.53 h35
  text "ESP32 Color Coin" at 1365.14,19.53 h35
Mechanical 1:
  pour cut-out: 1294.89,-1080
  lines w10: 0,50 ccw(c50,50) 50.5,0 1699.51,0 ccw(c1700.01,50) 1750.01,50 1749.99,1005.01 ccw(c1699.99,1005.01) 1699.49,1055 50.5,1055 ccw(c50,1005) 0,1005 0,50

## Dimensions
50.5,1055 to 50.5,0 on Drill Drawing
0,1005 to 1749.99,1005.01 on Drill Drawing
